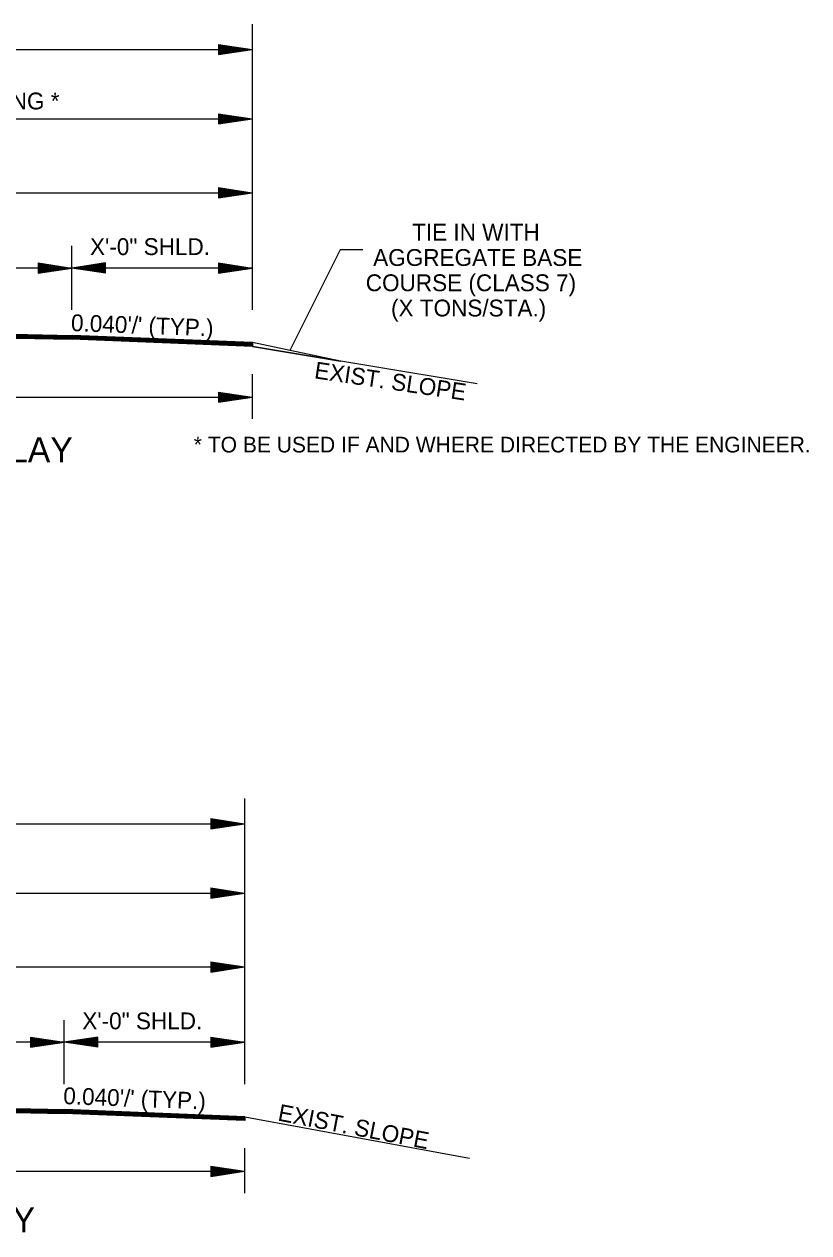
# Model space of a CAD drawing. Extents: x 544199 to 1930787, y -1968972 to 596640.
# Drawn here: x 552079 to 552428, y -1954563 to -1954024 of the extents above; entities that cross this region are included whole.
import ezdxf

# ---------------------------------------------------------------- set-up
doc = ezdxf.new("R2010")
doc.units = 0
doc.layers.add('R_Border Prem', color=7, linetype='Continuous')
doc.layers.add('R_Draft', color=7, linetype='Continuous')

msp = doc.modelspace()

# ---------------------------------------------------------------- linework, layer by layer
at = {"layer": 'R_Draft'}
for p, q in [((551780.08, -1954035.53), (552180.53, -1954035.53)), ((552165.53, -1954033.28), (552180.53, -1954035.53)), ((552165.53, -1954033.28), (552165.53, -1954037.78)), ((552165.53, -1954033.66), (552178.03, -1954035.53)), ((552165.53, -1954034.04), (552175.45, -1954035.53)), ((552165.53, -1954034.42), (552172.95, -1954035.53)), ((552165.53, -1954034.81), (552170.41, -1954035.53)), ((552165.53, -1954035.18), (552167.9, -1954035.53)), ((552165.53, -1954037.78), (552180.53, -1954035.53)), ((552165.53, -1954036.27), (552170.41, -1954035.53)), ((552165.53, -1954037.03), (552175.45, -1954035.53)), ((552165.53, -1954037.41), (552178.03, -1954035.53)), ((552165.53, -1954036.65), (552172.95, -1954035.53)), ((552165.53, -1954035.89), (552167.9, -1954035.53)), ((552165.53, -1954064.15), (552180.53, -1954066.4)), ((552165.53, -1954064.15), (552165.53, -1954068.65)), ((551780.08, -1954066.4), (552180.53, -1954066.4)), ((552165.53, -1954064.53), (552178.03, -1954066.4)), ((552165.53, -1954064.91), (552175.45, -1954066.4)), ((552165.53, -1954065.29), (552172.95, -1954066.4)), ((552165.53, -1954065.68), (552170.41, -1954066.4)), ((552165.53, -1954066.05), (552167.9, -1954066.4)), ((552165.53, -1954068.65), (552180.53, -1954066.4)), ((552165.53, -1954067.14), (552170.41, -1954066.4)), ((552165.53, -1954067.9), (552175.45, -1954066.4)), ((552165.53, -1954068.28), (552178.03, -1954066.4)), ((552165.53, -1954067.52), (552172.95, -1954066.4)), ((552165.53, -1954066.76), (552167.9, -1954066.4)), ((551780.08, -1954099.33), (552180.53, -1954099.33)), ((552165.53, -1954097.08), (552180.53, -1954099.33)), ((552165.53, -1954097.08), (552165.53, -1954101.58)), ((552165.53, -1954097.46), (552178.03, -1954099.33)), ((552165.53, -1954097.84), (552175.45, -1954099.33)), ((552165.53, -1954098.22), (552172.95, -1954099.33)), ((552165.53, -1954098.61), (552170.41, -1954099.33)), ((552165.53, -1954098.98), (552167.9, -1954099.33)), ((552165.53, -1954101.58), (552180.53, -1954099.33)), ((552165.53, -1954100.07), (552170.41, -1954099.33)), ((552165.53, -1954100.83), (552175.45, -1954099.33)), ((552165.53, -1954101.21), (552178.03, -1954099.33)), ((552165.53, -1954100.45), (552172.95, -1954099.33)), ((552165.53, -1954099.69), (552167.9, -1954099.33)), ((552100.27, -1954132.87), (552100.27, -1954122.98)), ((552100.27, -1954151.53), (552100.27, -1954122.98)), ((552100.27, -1954132.87), (551980.34, -1954132.87)), ((552085.27, -1954130.62), (552100.27, -1954132.87)), ((552085.27, -1954130.62), (552085.27, -1954135.12)), ((552085.27, -1954131), (552097.77, -1954132.87)), ((552085.27, -1954131.38), (552095.19, -1954132.87)), ((552085.27, -1954131.75), (552092.69, -1954132.87)), ((552085.27, -1954132.14), (552090.15, -1954132.87)), ((552085.27, -1954132.52), (552087.64, -1954132.87)), ((552085.27, -1954135.12), (552100.27, -1954132.87)), ((552085.27, -1954133.61), (552090.15, -1954132.87)), ((552085.27, -1954134.36), (552095.19, -1954132.87)), ((552085.27, -1954134.75), (552097.77, -1954132.87)), ((552085.27, -1954133.99), (552092.69, -1954132.87)), ((552085.27, -1954133.22), (552087.64, -1954132.87)), ((552115.27, -1954130.62), (552100.27, -1954132.87)), ((552100.27, -1954151.53), (552100.27, -1954132.87)), ((552180.53, -1954132.87), (552100.27, -1954132.87)), ((552115.27, -1954135.12), (552100.27, -1954132.87)), ((552115.27, -1954131), (552102.78, -1954132.87)), ((552115.27, -1954134.75), (552102.78, -1954132.87)), ((552115.27, -1954131.38), (552105.36, -1954132.87)), ((552115.27, -1954134.36), (552105.36, -1954132.87)), ((552115.27, -1954131.75), (552107.85, -1954132.87)), ((552115.27, -1954133.99), (552107.85, -1954132.87)), ((552115.27, -1954132.14), (552110.4, -1954132.87)), ((552115.27, -1954133.6), (552110.4, -1954132.87)), ((552115.27, -1954132.52), (552112.9, -1954132.87)), ((552115.27, -1954133.22), (552112.9, -1954132.87)), ((552115.27, -1954135.12), (552115.27, -1954130.62)), ((552165.53, -1954130.62), (552180.53, -1954132.87)), ((552165.53, -1954130.62), (552165.53, -1954135.12)), ((552165.53, -1954131), (552178.03, -1954132.87)), ((552165.53, -1954131.38), (552175.45, -1954132.87)), ((552165.53, -1954131.75), (552172.95, -1954132.87)), ((552165.53, -1954132.14), (552170.41, -1954132.87)), ((552165.53, -1954132.52), (552167.9, -1954132.87)), ((552165.53, -1954135.12), (552180.53, -1954132.87)), ((552165.53, -1954133.61), (552170.41, -1954132.87)), ((552165.53, -1954134.36), (552175.45, -1954132.87)), ((552165.53, -1954134.75), (552178.03, -1954132.87)), ((552165.53, -1954133.99), (552172.95, -1954132.87)), ((552165.53, -1954133.22), (552167.9, -1954132.87)), ((551980.33, -1954161.08), (552100.33, -1954163.48)), ((551980.33, -1954161.38), (552100.33, -1954163.78)), ((551980.34, -1954160.48), (552100.34, -1954162.88)), ((551980.34, -1954160.78), (552100.34, -1954163.18)), ((551980.31, -1954161.98), (552100.31, -1954164.38)), ((551980.31, -1954162.18), (552100.31, -1954164.58)), ((551980.32, -1954161.68), (552100.32, -1954164.08)), ((552180.6, -1954167.59), (552100.28, -1954164.38)), ((552180.6, -1954167.79), (552100.28, -1954164.58)), ((552180.6, -1954167.29), (552100.3, -1954164.08)), ((552180.6, -1954166.99), (552100.31, -1954163.78)), ((552180.6, -1954166.69), (552100.32, -1954163.48)), ((552180.6, -1954166.39), (552100.33, -1954163.18)), ((552180.6, -1954166.09), (552100.34, -1954162.88)), ((552180.6, -1954167.79), (552180.6, -1954166.09)), ((552180.6, -1954166.09), (552180.6, -1954167.79)), ((552219.85, -1954174.32), (552180.6, -1954166.09)), ((552180.6, -1954166.09), (552180.6, -1954167.79)), ((552180.6, -1954167.79), (552180.6, -1954166.09)), ((552280.67, -1954184.46), (552180.6, -1954167.79)), ((552180.6, -1954167.79), (552180.6, -1954167.79)), ((552180.6, -1954167.79), (552219.85, -1954174.32)), ((552180.53, -1954180.09), (552180.53, -1954200.09)), ((552165.53, -1954188.09), (552180.53, -1954190.34)), ((552165.53, -1954188.09), (552165.53, -1954192.59)), ((551780.08, -1954190.34), (552180.53, -1954190.34)), ((552165.53, -1954188.46), (552178.03, -1954190.34)), ((552165.53, -1954188.84), (552175.45, -1954190.34)), ((552165.53, -1954189.22), (552172.95, -1954190.34)), ((552165.53, -1954189.61), (552170.41, -1954190.34)), ((552165.53, -1954189.98), (552167.9, -1954190.34)), ((552165.53, -1954192.59), (552180.53, -1954190.34)), ((552165.53, -1954191.07), (552170.41, -1954190.34)), ((552165.53, -1954191.83), (552175.45, -1954190.34)), ((552165.53, -1954192.21), (552178.03, -1954190.34)), ((552165.53, -1954191.45), (552172.95, -1954190.34)), ((552165.53, -1954190.69), (552167.9, -1954190.34)), ((551776.65, -1954380.33), (552177.1, -1954380.33)), ((552162.1, -1954378.08), (552177.1, -1954380.33)), ((552162.1, -1954378.08), (552162.1, -1954382.58)), ((552162.1, -1954378.45), (552174.6, -1954380.33)), ((552162.1, -1954378.84), (552172.02, -1954380.33)), ((552162.1, -1954379.21), (552169.52, -1954380.33)), ((552162.1, -1954379.6), (552166.98, -1954380.33)), ((552162.1, -1954379.98), (552164.47, -1954380.33)), ((552162.1, -1954382.58), (552177.1, -1954380.33)), ((552162.1, -1954381.06), (552166.98, -1954380.33)), ((552162.1, -1954381.82), (552172.02, -1954380.33)), ((552162.1, -1954382.2), (552174.6, -1954380.33)), ((552162.1, -1954381.45), (552169.52, -1954380.33)), ((552162.1, -1954380.68), (552164.47, -1954380.33)), ((552162.1, -1954408.95), (552177.1, -1954411.2)), ((552162.1, -1954408.95), (552162.1, -1954413.45)), ((551776.65, -1954411.2), (552177.1, -1954411.2)), ((552162.1, -1954409.32), (552174.6, -1954411.2)), ((552162.1, -1954409.71), (552172.02, -1954411.2)), ((552162.1, -1954410.08), (552169.52, -1954411.2)), ((552162.1, -1954410.47), (552166.98, -1954411.2)), ((552162.1, -1954410.85), (552164.47, -1954411.2)), ((552162.1, -1954413.45), (552177.1, -1954411.2)), ((552162.1, -1954411.93), (552166.98, -1954411.2)), ((552162.1, -1954412.69), (552172.02, -1954411.2)), ((552162.1, -1954413.07), (552174.6, -1954411.2)), ((552162.1, -1954412.32), (552169.52, -1954411.2)), ((552162.1, -1954411.55), (552164.47, -1954411.2)), ((551776.65, -1954444.13), (552177.1, -1954444.13)), ((552162.1, -1954441.88), (552177.1, -1954444.13)), ((552162.1, -1954441.88), (552162.1, -1954446.38)), ((552162.1, -1954442.25), (552174.6, -1954444.13)), ((552162.1, -1954442.63), (552172.02, -1954444.13)), ((552162.1, -1954443.01), (552169.52, -1954444.13)), ((552162.1, -1954443.4), (552166.98, -1954444.13)), ((552162.1, -1954443.77), (552164.47, -1954444.13)), ((552162.1, -1954446.38), (552177.1, -1954444.13)), ((552162.1, -1954444.86), (552166.98, -1954444.13)), ((552162.1, -1954445.62), (552172.02, -1954444.13)), ((552162.1, -1954446), (552174.6, -1954444.13)), ((552162.1, -1954445.24), (552169.52, -1954444.13)), ((552162.1, -1954444.48), (552164.47, -1954444.13)), ((552096.84, -1954477.66), (552096.84, -1954467.77)), ((552096.84, -1954496.32), (552096.84, -1954467.77)), ((552096.84, -1954477.66), (551976.91, -1954477.66)), ((552081.84, -1954475.41), (552096.84, -1954477.66)), ((552081.84, -1954475.41), (552081.84, -1954479.91)), ((552081.84, -1954475.79), (552094.34, -1954477.66)), ((552081.84, -1954476.17), (552091.76, -1954477.66)), ((552081.84, -1954476.55), (552089.26, -1954477.66)), ((552081.84, -1954476.94), (552086.72, -1954477.66)), ((552081.84, -1954477.31), (552084.21, -1954477.66)), ((552081.84, -1954479.91), (552096.84, -1954477.66)), ((552081.84, -1954478.4), (552086.72, -1954477.66)), ((552081.84, -1954479.16), (552091.76, -1954477.66)), ((552081.84, -1954479.54), (552094.34, -1954477.66)), ((552081.84, -1954478.78), (552089.26, -1954477.66)), ((552081.84, -1954478.02), (552084.21, -1954477.66)), ((552111.84, -1954475.41), (552096.84, -1954477.66)), ((552096.84, -1954496.32), (552096.84, -1954477.66)), ((552177.1, -1954477.66), (552096.84, -1954477.66)), ((552111.84, -1954479.91), (552096.84, -1954477.66)), ((552111.84, -1954475.79), (552099.35, -1954477.66)), ((552111.84, -1954479.54), (552099.35, -1954477.66)), ((552111.84, -1954476.17), (552101.93, -1954477.66)), ((552111.84, -1954479.16), (552101.93, -1954477.66)), ((552111.84, -1954476.55), (552104.42, -1954477.66)), ((552111.84, -1954478.78), (552104.42, -1954477.66)), ((552111.84, -1954476.93), (552106.97, -1954477.66)), ((552111.84, -1954478.39), (552106.97, -1954477.66)), ((552111.84, -1954477.31), (552109.47, -1954477.66)), ((552111.84, -1954478.02), (552109.47, -1954477.66)), ((552111.84, -1954479.91), (552111.84, -1954475.41)), ((552162.1, -1954475.41), (552177.1, -1954477.66)), ((552162.1, -1954475.41), (552162.1, -1954479.91)), ((552162.1, -1954475.79), (552174.6, -1954477.66)), ((552162.1, -1954476.17), (552172.02, -1954477.66)), ((552162.1, -1954476.55), (552169.52, -1954477.66)), ((552162.1, -1954476.94), (552166.98, -1954477.66)), ((552162.1, -1954477.31), (552164.47, -1954477.66)), ((552162.1, -1954479.91), (552177.1, -1954477.66)), ((552162.1, -1954478.4), (552166.98, -1954477.66)), ((552162.1, -1954479.16), (552172.02, -1954477.66)), ((552162.1, -1954479.54), (552174.6, -1954477.66)), ((552162.1, -1954478.78), (552169.52, -1954477.66)), ((552162.1, -1954478.02), (552164.47, -1954477.66)), ((551976.9, -1954505.87), (552096.9, -1954508.27)), ((551976.91, -1954505.27), (552096.91, -1954507.67)), ((551976.91, -1954505.57), (552096.91, -1954507.97)), ((551976.88, -1954506.77), (552096.88, -1954509.17)), ((551976.88, -1954506.97), (552096.88, -1954509.37)), ((551976.89, -1954506.47), (552096.89, -1954508.87)), ((551976.9, -1954506.17), (552096.9, -1954508.57)), ((552177.18, -1954512.58), (552096.85, -1954509.37)), ((552177.18, -1954512.38), (552096.86, -1954509.17)), ((552177.18, -1954512.08), (552096.87, -1954508.87)), ((552177.18, -1954511.78), (552096.88, -1954508.57)), ((552177.18, -1954511.48), (552096.89, -1954508.27)), ((552177.18, -1954511.18), (552096.9, -1954507.97)), ((552177.18, -1954510.88), (552096.91, -1954507.67)), ((552177.18, -1954512.58), (552177.18, -1954510.88)), ((552177.18, -1954510.88), (552177.18, -1954512.58)), ((552177.18, -1954510.88), (552277.24, -1954529.26)), ((552177.1, -1954524.88), (552177.1, -1954544.88)), ((551776.65, -1954535.13), (552177.1, -1954535.13)), ((552162.1, -1954532.88), (552177.1, -1954535.13)), ((552162.1, -1954532.88), (552162.1, -1954537.38)), ((552162.1, -1954533.25), (552174.6, -1954535.13)), ((552162.1, -1954533.64), (552172.02, -1954535.13)), ((552162.1, -1954534.01), (552169.52, -1954535.13)), ((552162.1, -1954534.4), (552166.98, -1954535.13)), ((552162.1, -1954534.78), (552164.47, -1954535.13)), ((552162.1, -1954537.38), (552177.1, -1954535.13)), ((552162.1, -1954535.86), (552166.98, -1954535.13)), ((552162.1, -1954536.62), (552172.02, -1954535.13)), ((552162.1, -1954537), (552174.6, -1954535.13)), ((552162.1, -1954536.25), (552169.52, -1954535.13)), ((552162.1, -1954535.48), (552164.47, -1954535.13))]:
    msp.add_line(p, q, dxfattribs=at)
for points in [[(552180.53, -1954024.27), (552180.53, -1954151.53)], [(552229.73, -1954124.79), (552219.73, -1954124.79), (552197.2, -1954169.57)], [(552177.1, -1954369.07), (552177.1, -1954496.32)]]:
    msp.add_lwpolyline(points, dxfattribs=at)

# ---------------------------------------------------------------- texts
at = {"layer": 'R_Border Prem'}
msp.add_text('* TO BE USED IF AND WHERE DIRECTED BY THE ENGINEER.', height=7, dxfattribs=at).set_placement((552154.5, -1954215.01))
at = {"layer": 'R_Draft'}
for s, height, p in [('XX\'-X" ACHM SURFACE COURSE (1/2") FOR LEVELING *', 7.5, (551827.68, -1954062.24)), ('TIE IN WITH ', 7.5, (552251.67, -1954120.69)), ('X\'-0" SHLD.', 7.5, (552108.31, -1954127.1)), ('AGGREGATE BASE', 7.5, (552234.36, -1954131.94)), ('COURSE (CLASS 7)', 7.5, (552231.06, -1954143.19)), ('(X TONS/STA.)', 7.5, (552242.28, -1954154.44)), ('2 LANE OPEN SHOULDER OVERLAY', 11.25, (551839.01, -1954219.45)), ('X\'-0" SHLD.', 7.5, (552104.88, -1954471.89)), ('2 LANE OPEN SHOULDER INLAY', 11.25, (551849.75, -1954562.37))]:
    msp.add_text(s, height=height, dxfattribs=at).set_placement(p)
for s, rotation, p in [("0.040'/' (TYP.)", 357.8168, (552099.74, -1954160.92)), ('EXIST. SLOPE', 351.5755, (552207.85, -1954181.94)), ("0.040'/' (TYP.)", 357.8168, (552096.31, -1954505.18)), ('EXIST. SLOPE', 349.1171, (552191.57, -1954512.48))]:
    msp.add_text(s, height=7.5, rotation=rotation, dxfattribs=at).set_placement(p)

doc.saveas('drawing.dxf')
